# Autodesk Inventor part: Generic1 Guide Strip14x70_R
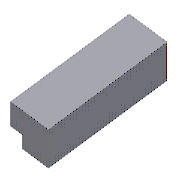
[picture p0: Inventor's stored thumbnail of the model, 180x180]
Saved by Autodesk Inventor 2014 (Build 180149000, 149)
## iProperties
IsCustomPart: 1
Created: 2009-11
Part Number: Generic1 Guide Strip14x70_R
Material: DIN 1.2842
Description: Guide Rail
Document SubType Name: Modeling
Designer: gaom
Standard Revision: 1
Manufacturer: Generic
Language: en-US
Size Designation: 14x70_R
Categories: <MemberInstance><Categories><Category DisplayName="Mold" InternalName="349578f2-f4d4-4954-8c09-8e99297a61c0" Mnemonic="MOLD"><Category DisplayName="Slide Compon
Density: 7.66 g/cm^3
Appearance: Polished - Brushed Heavy-1-1-1-1-1-1-1-1-1-1-1-1-1-1
Position: L
Part Type: 2
Author: gaom
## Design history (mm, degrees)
sketch "Sketch1"
  geometry: L1 (0, -6)-(0, 8) reference; L2 (-20, 6)-(-34, 6); L3 (-34, 6)-(-34, -4); L4 (-34, -4)-(-25, -4); L5 (-25, -4)-(-25, 0); L6 (-25, 0)-(-20, 0); L7 (-20, 0)-(-20, 6); 1 further point
  constraints: 12 end point, 3 horizontal, 3 vertical, 1 horizontal alignment
  dimensions: "d235" = 14 distance of L2.start L2.end (derived); "d236" = 10 distance of L2.end L3.end (derived); "d237" = 5 distance of L5.end L6.end (derived); "d238" = 4 distance of L4.end L5.end (derived); "d239" = 20 distance between parallel lines of L7 L1 (derived)
extrude "Extrusion_L" new body sketch "Sketch1" distance "d27" = 70 (= GS_l1); taper "d28" = 0 deg
sketch "Sketch4"
  geometry: L1 (20, 0)-(20, 6); L2 (20, 6)-(34, 6); L3 (34, 6)-(34, -4); L4 (34, -4)-(25, -4); L5 (25, -4)-(25, 0); L6 (20, 0)-(25, 0); L7 (0, 8)-(0, -6) reference; 1 further point
  constraints: 12 end point, 3 parallel, 1 horizontal, 1 horizontal alignment, 1 perpendicular, 1 vertical
  dimensions: "d101" = 10 distance between parallel lines of L4 L2 (= GS_h2); "d240" = 14 distance of L1.end L2.end (derived); "d241" = 4 distance of L4.end L5.end (derived); "d242" = 5 distance of L1.start L5.end (derived); "d243" = 20 distance between parallel lines of L1 L7 (derived)
extrude "Extrusion_R" new body sketch "Sketch4" distance "d107" = 70 (derived); taper "d108" = 0 deg
body "Solid1"
workplane "Work Plane1"
feature "Stitch Surface1" dims "d272" = 0.254 (derived)
workplane "Work Plane2"
feature "Stitch Surface2" dims "d273" = 0.254 (derived)
sketch "Sketch2"
  geometry: L1 (0, 14)-(0, 0); L2 (170, 14)-(170, 0); L3 (70, 0)-(70, 14) reference; L4 (0, 14)-(70, 14) reference; L5 (0, 0)-(70, 0) reference; L6 (0, 14)-(170, 14); L7 (0, 0)-(170, 0); 3 further points
  constraints: 8 end point, 3 point on line, 2 horizontal, 2 midpoint, 2 vertical
  dimensions: "d255" = 100 distance between parallel lines of L3 L2 (derived)
body "Srf1"
body "Srf2"
body "Srf3"
body "Srf4"
sketch "Sketch5"
  geometry: L1 (0, 14)-(170, 14); L2 (170, 14)-(170, 0); L3 (170, 0)-(0, 0); L4 (0, 0)-(0, 14); L5 (0, 14)-(70, 14) reference; L6 (70, 0)-(70, 14) reference; L7 (0, 0)-(70, 0) reference; 2 further points
  constraints: 8 end point, 6 point on line, 2 parallel, 1 collinear, 1 horizontal, 1 midpoint, 1 perpendicular
  dimensions: "d136" = 100 distance between parallel lines of L2 L6 (derived)
body "Srf5"
body "Srf6"
body "Srf7"
body "Srf8"
extrude_surface "ExtrusionSrf1" dims "d81" = 10.5 (derived), "d82" = 0
patch "Boundary Patch1" dims "d84" = 0, "d256" = 0, "d257" = 0, "d258" = 0, "d259" = 0
patch "Boundary Patch2" dims "d86" = 0, "d260" = 0, "d261" = 0, "d262" = 0, "d263" = 0
extrude_surface "ExtrusionSrf3" dims "d138" = 10.5 (derived), "d139" = 0
patch "Boundary Patch5" dims "d250" = 0, "d264" = 0, "d265" = 0, "d266" = 0, "d267" = 0
patch "Boundary Patch6" dims "d252" = 0, "d268" = 0, "d269" = 0, "d270" = 0, "d271" = 0
other parameters: "GS_b" = 14 [user parameter], "GS_l1" = 70 [user parameter; used in 1 equation term], "GS_h2" = 10 [user parameter; used in 1 equation term], "GS_t1" = 5 [user parameter], "GS_h3" = 4 [user parameter], "GS_es1" = 0.5 [user parameter; used in 1 equation term], "GS_esr" = 2.5 [user parameter], "GS_esw" = 5 [user parameter], "GS_esl1" = 5 [user parameter], "d96" = 0.5 (= GS_es1), "d134" = 0.5 (derived)
